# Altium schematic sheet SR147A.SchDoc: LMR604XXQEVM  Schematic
size 431 x 279 mm; Date: Not shown in title block; ApprovedBy: Not shown in title block; CheckedBy: Not shown in title block; Author: Not shown in title block; CompanyName: Not shown in title block; DrawnBy: R Fu; Engineer: Not shown in title block; Organization: Not shown in title block; Address1: Not shown in title block; Address2: Not shown in title block; Address3: Not shown in title block; Address4: Not shown in title block; DocumentNumber: 2; Revision: Use project parameter SCH_Rev; SheetNumber: 2; SheetTotal: 2; PageSetup: Record=PageOptions¦CenterHorizontal=True¦CenterVertical=True¦PrintScale=1.00¦XCorrection=1.00¦YCorrection=1.00¦PrintKind=0¦BorderSize=5000000¦LeftOffset=0¦BottomOffset=0¦Orientation=2¦PaperLength=1000¦PaperWidth=1000¦Scale=100¦PaperSource=15¦PrintQuality=600¦MediaType=1¦DitherType=10¦PaperKind=Letter¦PrintScaleMode=1
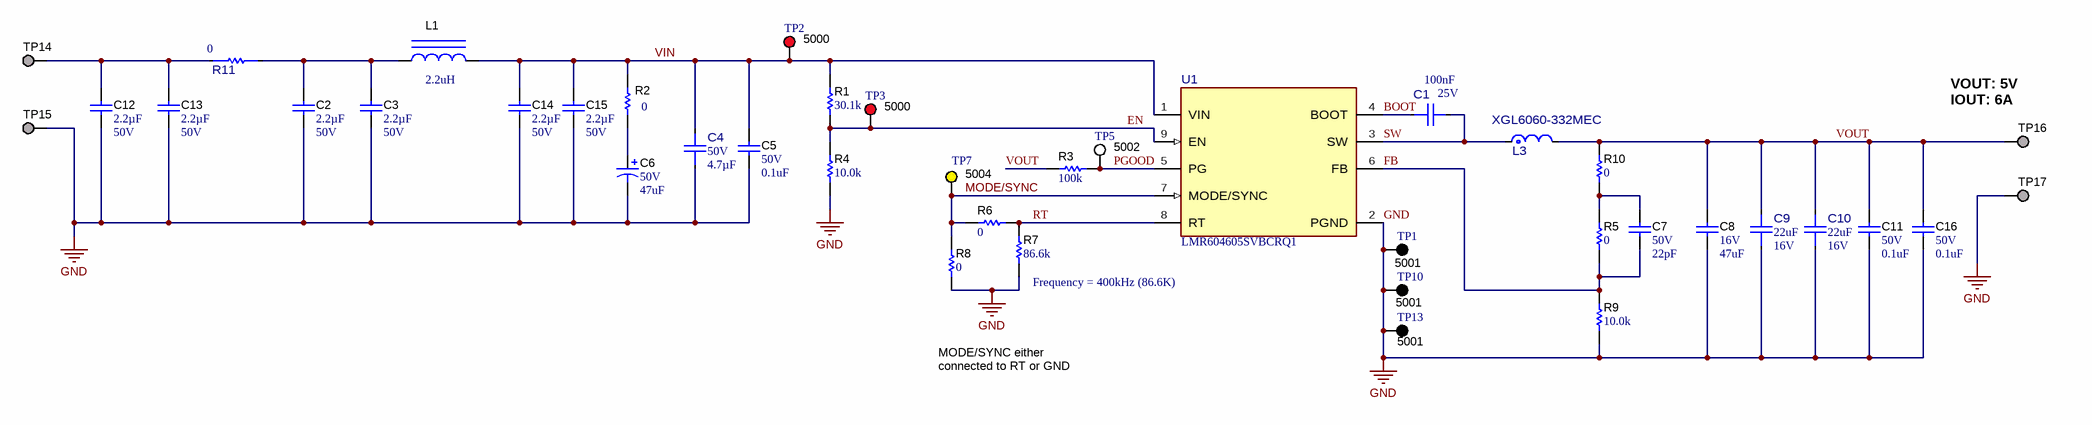
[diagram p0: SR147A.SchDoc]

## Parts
C1  ValueDisplayed: 100nF  VDC_V: 25V  [FP-CS0402KRX7R8BB104_0402-MFG]  (hidden comment: CS0402KRX7R8BB104)
C2  Cap_F: 2.2µF  VDC_V: 50V  [0805_HV]  (hidden comment: CGA4J3X7R1H225K125AB)
C3  Cap_F: 2.2µF  VDC_V: 50V  [0805_HV]  (hidden comment: CGA4J3X7R1H225K125AB)
C4  VDC_V: 50V  Cap_F: 4.7µF  [FP-C2012X7R1H475K125AC_0805-MFG]  (hidden comment: C2012X7R1H475K125AC)
C5  VDC_V: 50V  ValueDisplayed: 0.1uF  [0402]  (hidden comment: GCM155R71H104KE02D)
C6  VDC_V: 50V  ValueDisplayed: 47uF  [Panasonic_D]  (hidden comment: EEEFT1H470AP)
C7  VDC_V: 50V  ValueDisplayed: 22pF  [0402]  (hidden comment: CGA2B2C0G1H220J050BA)
C8  VDC_V: 16V  ValueDisplayed: 47uF  [1210_270]  (hidden comment: GRM32ER61C476KE15L)
C9  ValueDisplayed: 22uF  VDC_V: 16V  [FP-CGA6P1X7R1C226M250AC_1210-MFG]  (hidden comment: CGA6P1X7R1C226M250AC)
C10  ValueDisplayed: 22uF  VDC_V: 16V  [FP-CGA6P1X7R1C226M250AC_1210-MFG]  (hidden comment: CGA6P1X7R1C226M250AC)
C11  VDC_V: 50V  ValueDisplayed: 0.1uF  [0402]  (hidden comment: GCM155R71H104KE02D)
C12  Cap_F: 2.2µF  VDC_V: 50V  [0805_HV]  (hidden comment: CGA4J3X7R1H225K125AB)
C13  Cap_F: 2.2µF  VDC_V: 50V  [0805_HV]  (hidden comment: CGA4J3X7R1H225K125AB)
C14  Cap_F: 2.2µF  VDC_V: 50V  [0805L]  (hidden comment: CGA4J3X7R1H225K125AB)
C15  Cap_F: 2.2µF  VDC_V: 50V  [0805L]  (hidden comment: CGA4J3X7R1H225K125AB)
C16  VDC_V: 50V  ValueDisplayed: 0.1uF  [0402S]  (hidden comment: GCM155R71H104KE02D)
L1  ValueDisplayed: 2.2uH  [XEL4020]  (hidden comment: XEL4020-222MEB)
L3  XGL6060-332MEC  [FP-XGL6060-332MEC_SMT_6MM51_6MM71-MFG]
R1  ValueDisplayed: 30.1k  [0402L]  (hidden comment: CRCW040230K1FKED)
R2  value 0  [0402L]  (hidden comment: RC0402JR-070RL)
R3  ValueDisplayed: 100k  [0402L]  (hidden comment: CRCW0402100KJNED)
R4  ValueDisplayed: 10.0k  [0402L]  (hidden comment: AC0402FR-0710KL)
R5  ValueDisplayed: 0  [0402L]  (hidden comment: RC0402JR-070RL)
R6  ValueDisplayed: 0  [0402L]  (hidden comment: RC0402JR-070RL)
R7  ValueDisplayed: 86.6k  [0402L]  (hidden comment: CRCW040286K6FKED)
R8  ValueDisplayed: 0  [0402L]  (hidden comment: RC0402JR-070RL)
R9  ValueDisplayed: 10.0k  [0402L]  (hidden comment: MCS0402MD1002BE100)
R10  ValueDisplayed: 0  [0402L]  (hidden comment: RC0402JR-070RL)
R11  value 0  [FP-5108_1206-MFG]  (hidden comment: 5108)
TP1  5001  [Keystone5001]
TP2  5000  [Keystone5000]
TP3  5000  [Keystone5000]
TP5  5002  [Keystone5002]
TP7  5004  [Keystone5004]
TP10  5001  [Keystone5001]
TP13  5001  [Keystone5001]
TP14  1502-2  [Keystone1502-2]  (value not drawn)
TP15  1502-2  [Keystone1502-2]  (value not drawn)
TP16  1502-2  [Keystone1502-2]  (value not drawn)
TP17  1502-2  [Keystone1502-2]  (value not drawn)
U1  PartNumber: LMR604605SVBCRQ1  [VBC0009A-MFG]  (hidden comment: LMR604605SVBC)

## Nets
GND: C2.2 C3.2 C4.1 C5.2 C6.2(-) C8.2 C9.1 C10.1 C11.2 C12.2 C13.2 C14.2 C15.2 C16.2 R4.1 R7.1 R8.1 R9.1 TP1.1 TP10.1 TP13.1 TP15.1 TP17.1 U1.2(PGND)
BOOT: C1.1 U1.4(BOOT)
EN: R1.1 R4.2 TP3.1 U1.9(EN)
FB: C7.2 R5.1 R9.2 U1.6(FB)
MODE/SYNC: R6.2 R8.2 TP7.1 U1.7(MODE/SYNC)
PGOOD: R3.2 TP5.1 U1.5(PG)
RT: R6.1 R7.2 U1.8(RT)
SW: C1.2 L3.1 U1.3(SW)
VIN: C4.2 C5.1 C14.1 C15.1 L1.2 R1.2 R2.2 TP2.1 U1.1(VIN)
VOUT: C8.1 C9.2 C10.2 C11.1 C16.1 L3.2 R3.1 R10.2 TP16.1
NetC2_1: C2.1 C3.1 L1.1 R11.2
NetC6_1: C6.1(+) R2.1
NetC7_1: C7.1 R5.2 R10.1
NetC12_1: C12.1 C13.1 R11.1 TP14.1

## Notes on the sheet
- (near TP14) VIN: 8V-36V
- (near TP16) VOUT: 5V
  IOUT: 6A
- (near R7) Frequency = 400kHz (86.6K)
- MODE/SYNC either connected to RT or GND

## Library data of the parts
C1 = CMP-0050130-1: 0.1 µF ±10% 25V Ceramic Capacitor X7R 0402 (1005 Metric); Manufacturer: Yageo; AEC Qualified: No; SizeZ_mm: 0.65mm; TempCo: 15%; Value: 100nF
C2 C3 C12-C15 = CMP-0007977-2: CAP, CERM, 2.2 uF, 50 V, +/- 10%, X7R, AEC-Q200 Grade 1, 0805; Manufacturer: TDK; TaMin_C: -55°C; ESR_ohm: 3.288m; Polarized: N; SizeAreaWB_mm2: 6.75; Value1: 0.003288 ohm; U/M: EA; Value: 2.2uF; TaMax_C: 125°C; SizeZ_mm: 1.45; SizeX_mm: 2; SizeY_mm: 1.25; Cap_Case: 0805; SizeArea_mm2: 2.5; AEC Qualified: Y; IRMS_A: 3.6003A; AEC Grade: 1; AEC Category: Q200
C4 = CMP-0088943-1: 4.7µF ±10% 50V Ceramic Capacitor X7R 0805 (2012 Metric); Manufacturer: TDK; TempCo: 15%; AEC Qualified: No; ValueDisplayed: 4.7uF; SizeZ_mm: 1.5mm
C5 C11 = CMP-0006356-2: CAP, CERM, 0.1 uF, 50 V, +/- 10%, X7R, AEC-Q200 Grade 1, 0402; Manufacturer: MuRata; TaMin_C: -55°C; Polarized: N; SizeAreaWB_mm2: 3; Value1: Unknown; U/M: EA; Value: 0.1uF; TaMax_C: 125°C; SizeZ_mm: 0.6; SizeX_mm: 1; SizeY_mm: 0.5; AEC Qualified: Y; Cap_F: 100nF; AEC Category: Q200
C6 = CMP-0011204-2: CAP, AL, 47 uF, 50 V, +/- 20%, 0.68 ohm, AEC-Q200 Grade 2, SMD; Manufacturer: Panasonic; TaMin_C: -55°C; ESR_ohm: 0.68; Polarized: Y; SizeAreaWB_mm2: 73.96; U/M: EA; Value: 47uF; TaMax_C: 105°C; SizeZ_mm: 6.1; SizeX_mm: 6.6; Cap_Case: 6.3x5.8mm; SizeArea_mm2: 43.56; CompType: Capacitor; Cap_F: 47µF; IRMS_A: 195mA; AEC Grade: 2; AEC Category: Q200
C7 = CMP-0860831-1: CAP, CERM, 22 pF, 50 V,+/- 5%, C0G/NP0, AEC-Q200 Grade 1, 0402; Manufacturer: TDK; AEC Grade: 1; AEC Category: Q200; TaMin_C: -55°C; SizeY_mm: 0.5; Polarized: N; U/M: EA; SizeZ_mm: 0.6; AEC Qualified: Y; SizeAreaWB_mm2: 3; TaMax_C: 125°C; Value: 22pF
C8 = CMP-0009211-2: CAP, CERM, 47 uF, 16 V, +/- 10%, X5R, 1210; Manufacturer: MuRata; TaMin_C: -55°C; Polarized: N; SizeAreaWB_mm2: 14.7; Value1: Unknown; U/M: EA; Value: 47uF; TaMax_C: 85°C; SizeZ_mm: 2.7; SizeX_mm: 3.2; SizeY_mm: 2.5; Cap_Case: 1210; SizeArea_mm2: 8; Cap_F: 47µF; AEC Category: Q200
C9 C10 = CMP-0043794-1: Cap Ceramic 22uF 16V X7R 20% Pad SMD 1210 +125°C Automotive T/R; Manufacturer: TDK; AEC Grade: Grade 1; AEC Qualified: Yes; Cap_F: 22µF; SizeZ_mm: 2.8mm; TempCo: 15%; Tolerance_%: 0.2%; Value: 22µF
C16 = CMP-0006356-2: CAP, CERM, 0.1 uF, 50 V, +/- 10%, X7R, AEC-Q200 Grade 1, 0402; Manufacturer: MuRata; TaMin_C: -55°C; Polarized: N; SizeAreaWB_mm2: 3; Value1: Unknown; U/M: EA; Value: 0.1uF; TaMax_C: 125°C; SizeZ_mm: 0.6; SizeX_mm: 1; SizeY_mm: 0.5; Cap_Case: 0402; AEC Qualified: Y; Cap_F: 100nF; AEC Category: Q200
L1 = CMP-0061079-2: Inductor, Shielded, Composite, 2.2 uH, 5.5 A, 0.0362 ohm, AEC-Q200 Grade 1, SMD; Manufacturer: Coilcraft; Isat: 5.9A @ 30% inductance drop; Irms: 5.5A @ 40C rise; SizeAreaWB_mm2: 25; DCR_ohm: 36.2m; Value: 2.2uH; Imax_A: 5.5A; SizeZ_mm: 2.1; SizeX_mm: 4; SizeArea_mm2: 16; Ind_H: 2.2µH; AEC Qualified: Y; AEC Grade: 1; AEC Category: Q200
L3 = CMP-0093175-1: Shielded Power Inductors 3.3uH 20% tol, 6.5mOhm 16.6A; Manufacturer: Coilcraft; Shrouded: true; AEC Grade: Grade 1; TaMin_C: -40°C; Ind_H: 3.3µH; Test Frequency: 1MHz; DCR_ohm: 6.5m; Isat: 6.6A; Material: Composite; Self Resonant Frequency: 24MHz; SizeZ_mm: 6.1mm; AEC Qualified: Yes; TaMax_C: +125°C
R1 = CMP-0026284-2: RES, 30.1 k, 1%, 0.063 W, AEC-Q200 Grade 0, 0402; Manufacturer: Vishay-Dale; Power_W: 63mW; TempCo: 100 ppm/C; Value_Code: 30k1; Value: 30.1k; EIA_Code: E96; SizeX_mm: 1; SizeY_mm: 0.5; SizeZ_mm: 0.6; Value2: 0.063W; AEC Qualified: Y; VDC_V: 50V; AEC Category: Q200; AEC Grade: 0
R2 = CMP-0027004-2: RES, 0, 5%, 0.063 W, 0402; Manufacturer: Yageo America; SizeZ_mm: 0.6; Power_W: 63mW; TempCo: 200 ppm/C; Value_Code: 0000; U/M: EA; EIA_Code: E24; SizeX_mm: 1; SizeY_mm: 0.5; Value2: 0.063W; VDC_V: 50V; AEC Category: Q200
R3 = CMP-0026823-3: RES, 100 k, 5%, 0.063 W, AEC-Q200 Grade 0, 0402; Manufacturer: Vishay-Dale; Power_W: 63mW; TempCo: 200 ppm/C; Value: 100k; EIA_Code: E24; SizeX_mm: 1; SizeY_mm: 0.5; SizeZ_mm: 0.6; Value2: 0.063W; AEC Qualified: Y; VDC_V: 50V; AEC Category: Q200; AEC Grade: 0
R4 = CMP-0077731-1: RES, 10.0 k, 1%, 0.063 W, AEC-Q200 Grade 0, 0402; Manufacturer: Yageo America; Power_W: 63mW; TempCo: 100 ppm/C; Value_Code: 10k0; U/M: EA; Value: 10.0k; EIA_Code: E96; Res_ohm: 10k; SizeX_mm: 1.0; SizeY_mm: 0.5; SizeZ_mm: 0.6; Value2: 0.063W; AEC Qualified: Y; VDC_V: 50V; AEC Grade: 0; AEC Category: Q200
R5 R6 R8 R10 = CMP-0027004-2: RES, 0, 5%, 0.063 W, 0402; Manufacturer: Yageo America; Power_W: 63mW; TempCo: 200 ppm/C; Value_Code: 0000; U/M: EA; Value: 0; EIA_Code: E24; SizeX_mm: 1; SizeY_mm: 0.5; SizeZ_mm: 0.6; Value2: 0.063W; VDC_V: 50V; AEC Category: Q200
R7 = CMP-0026582-2: RES, 86.6 k, 1%, 0.063 W, AEC-Q200 Grade 0, 0402; Manufacturer: Vishay-Dale; Power_W: 63mW; TempCo: 100 ppm/C; Value_Code: 86k6; Value: 86.6k; EIA_Code: E96; SizeX_mm: 1; SizeY_mm: 0.5; SizeZ_mm: 0.6; Value2: 0.063W; AEC Qualified: Y; VDC_V: 50V; AEC Category: Q200; AEC Grade: 0
R9 = CMP-0077124-1: RES, 10.0 k, 0.1%, 0.1 W, AEC-Q200 Grade 0, 0402; Manufacturer: Vishay/Beyschlag; Value_Code: 10k0; SizeArea_mm2: 0.5; AEC Qualified: Y; AEC Category: Q200; Res_ohm: 10k; Value: 10.0k; SizeZ_mm: 0.6; EIA_Code: E192; TempCo: 25 ppm/C; AEC Grade: 0; Power_W: 100mW; VDC_V: 50V; Value2: 0.1W; U/M: EA; SizeX_mm: 1.0
R11 = CMP-0122408-1: 0 Ohms Jumper 0.5W, 1/2W Chip Resistor 1206 (3216 Metric) - Metal Element; Manufacturer: Keystone; AEC Qualified: No; Power_W: 500mW; SizeZ_mm: 0.71mm
TP1 TP10 TP13 = CMP-0055138-2: Test Point, Miniature, Black, TH; Manufacturer: Keystone Electronics; ContactFinish: Silver; CNHeader: FALSE; Green_Lifecycle: Active; Green_REACh: Passed; CT: TRUE
TP2 TP3 = CMP-0055137-2: Test Point, Miniature, Red, TH; Manufacturer: Keystone Electronics; Green_REACh: Passed; CT: TRUE; ContactFinish: Silver; CNHeader: FALSE; Green_Lifecycle: Active
TP5 = CMP-0055139-2: Test Point, Miniature, White, TH; Manufacturer: Keystone Electronics; ContactFinish: Silver; Green_REACh: Passed; CT: TRUE; Green_Lifecycle: Active; CNHeader: FALSE
TP7 = CMP-0055141-2: Test Point, Miniature, Yellow, TH; Manufacturer: Keystone Electronics; CT: TRUE; ContactFinish: Silver; Green_Lifecycle: Active; CNHeader: FALSE; Green_REACh: Passed
TP14-TP17 = CMP-0055113-1: Terminal, Turret, TH, Double; Manufacturer: Keystone; CT: FALSE; Green_REACh: Passed; CompType: Turret Terminal; Green_Lifecycle: Active
U1 = CMP-0125639-1: Manufacturer: Texas Instruments; SizeZ_mm: 0.7mm; Standoff Height: 0mm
